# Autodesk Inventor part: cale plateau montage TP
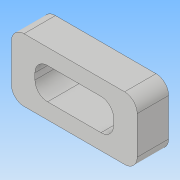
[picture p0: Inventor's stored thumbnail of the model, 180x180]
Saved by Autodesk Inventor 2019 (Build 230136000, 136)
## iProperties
Created: 2024-09
Part Number: cale plateau montage TP
Material: Générique
Document SubType Name: Modeling
Designer: admin
Density: 1 g/cm^3
Appearance: Par défaut
Author: admin
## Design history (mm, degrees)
sketch "Esquisse1"
  geometry: L1 (-18.773, 10.343)-(21.227, 10.343); L2 (21.227, 10.343)-(21.227, -9.657); L3 (21.227, -9.657)-(-18.773, -9.657); L4 (-18.773, -9.657)-(-18.773, 10.343); L5 (-11.273, 5.343)-(13.727, 5.343); L6 (13.727, 5.343)-(13.727, -4.657); L7 (13.727, -4.657)-(-11.273, -4.657); L8 (-11.273, -4.657)-(-11.273, 5.343); 1 further point
  constraints: 16 end point, 4 parallel, 2 horizontal, 2 perpendicular
  dimensions: "d0" = 40 distance of L1.start L1.end; "d1" = 20 distance of L3.end L1.start; "d2" = 25 distance of L5.start L5.end; "d3" = 10 distance of L7.end L5.start; "d4" = 5 distance between parallel lines of L1 L5; "d5" = 7.5 distance between parallel lines of L4 L8
extrude "Extrusion1" new body sketch "Esquisse1" distance "d6" = 10; taper "d7" = 0 deg
fillet "Congé1" dims "d8" = 4
node "Solide1"
